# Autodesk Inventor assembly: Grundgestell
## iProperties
Created: 2007-03
Part Number: Grundgestell
Cost Center: 218,57 kg
Document SubType Name: Assembly
Designer: Chako
Authority: 27843655 mm^3
SaveDate: 2007-03-16
SaveTime: 17:26
FileName: Grundgestell
TotalMass: 218,57 kg
TotalVolume: 27843655 mm^3
Author: Chako
